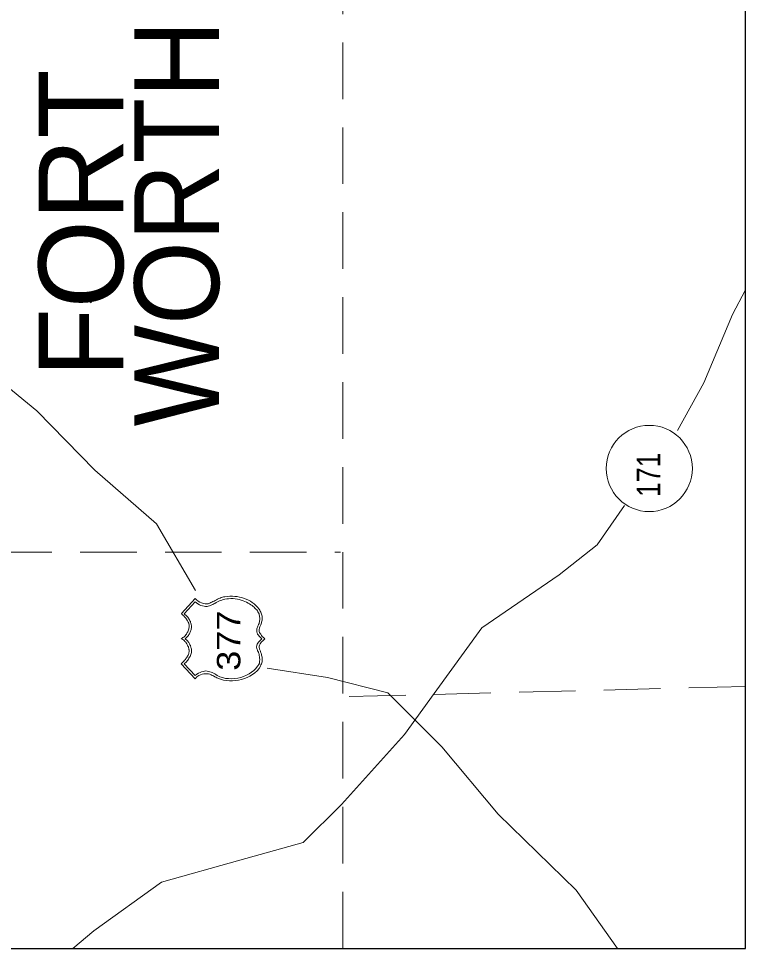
# Model space of a CAD drawing. Extents: x 2363323 to 2367082, y 6956018 to 6980837.
# Drawn here: x 2366076.4 to 2366234.3, y 6956633 to 6956834.9 of the extents above; entities that cross this region are included whole.
import ezdxf

# ---------------------------------------------------------------- set-up
doc = ezdxf.new("R2010")
doc.units = 0
doc.header["$LTSCALE"] = 4.1
doc.linetypes.add('MEDIUM_DASHED', pattern=[4.5, 3, -1.5])
doc.layers.add('62', color=7, linetype='Continuous', lineweight=13)
doc.layers.add('63', color=7, linetype='Continuous', lineweight=13)

msp = doc.modelspace()

# ---------------------------------------------------------------- linework, layer by layer
at = {"layer": '62', "linetype": 'MEDIUM_DASHED'}
for p, q in [((2366146.841, 6956632.956), (2366146.84, 6957082.55)), ((2365960.571, 6956719.006), (2366146.277, 6956719.029)), ((2366234.284, 6956689.842), (2366146.571, 6956687.637))]:
    msp.add_line(p, q, dxfattribs=at)
at = {"layer": '62'}
for p, q in [((2366093.962, 6956775.372), (2366091.959, 6956773.214)), ((2366225.284, 6956755.839), (2366219.503, 6956745.447)), ((2366202.061, 6956720.602), (2366208.046, 6956729.152)), ((2366106.337, 6956725.194), (2366114.819, 6956710.725)), ((2366193.803, 6956714.122), (2366202.061, 6956720.602))]:
    msp.add_line(p, q, dxfattribs=at)
at = {"layer": '62', "lineweight": 25}
msp.add_lwpolyline([(2365769.011, 6956632.956), (2366234.284, 6956632.956), (2366234.284, 6957082.548), (2365769.009, 6957082.548)], dxfattribs=at)
at = {"layer": '62'}
for points in [[(2366225.284, 6956755.839), (2366231.494, 6956770.67), (2366234.285, 6956775.98)], [(2366064.711, 6956763.894), (2366072.967, 6956755.728), (2366080.301, 6956749.743), (2366092.906, 6956736.826), (2366106.337, 6956725.194)], [(2366088.135, 6956632.958), (2366092.726, 6956636.76), (2366107.419, 6956647.359), (2366124.43, 6956652.129), (2366138.155, 6956655.932), (2366146.547, 6956664.212), (2366160.232, 6956679.424), (2366166.645, 6956688.357), (2366177.039, 6956702.6), (2366193.803, 6956714.122)], [(2366114.707, 6956691.53), (2366111.715, 6956694.792), (2366111.896, 6956694.972), (2366112.121, 6956695.174), (2366112.277, 6956695.354), (2366112.436, 6956695.534), (2366112.593, 6956695.714), (2366112.729, 6956695.917), (2366112.862, 6956696.097), (2366112.999, 6956696.277), (2366113.089, 6956696.457), (2366113.177, 6956696.637), (2366113.267, 6956696.838), (2366113.312, 6956697.02), (2366113.357, 6956697.222), (2366113.401, 6956697.38), (2366113.403, 6956697.582), (2366113.402, 6956697.784), (2366113.357, 6956697.92), (2366113.312, 6956698.077), (2366113.289, 6956698.257), (2366113.245, 6956698.437), (2366113.155, 6956698.618), (2366113.087, 6956698.797), (2366112.999, 6956698.954), (2366112.909, 6956699.134), (2366112.772, 6956699.316), (2366112.659, 6956699.474), (2366112.502, 6956699.63), (2366112.389, 6956699.787), (2366112.233, 6956699.924), (2366112.075, 6956700.034), (2366111.896, 6956700.124), (2366111.715, 6956700.216), (2366111.896, 6956700.327), (2366112.075, 6956700.462), (2366112.255, 6956700.574), (2366112.391, 6956700.734), (2366112.549, 6956700.868), (2366112.682, 6956701.047), (2366112.819, 6956701.227), (2366112.931, 6956701.384), (2366113.019, 6956701.566), (2366113.133, 6956701.748), (2366113.199, 6956701.95), (2366113.269, 6956702.128), (2366113.312, 6956702.355), (2366113.359, 6956702.511), (2366113.402, 6956702.736), (2366113.426, 6956702.938), (2366113.425, 6956703.096), (2366113.402, 6956703.274), (2366113.359, 6956703.432), (2366113.313, 6956703.638), (2366113.223, 6956703.794), (2366113.133, 6956703.974), (2366113.042, 6956704.132), (2366112.929, 6956704.311), (2366112.817, 6956704.467), (2366112.682, 6956704.672), (2366112.547, 6956704.83), (2366112.391, 6956705.007), (2366112.232, 6956705.168), (2366112.052, 6956705.368), (2366111.896, 6956705.504), (2366111.716, 6956705.684), (2366114.707, 6956708.948), (2366115.023, 6956708.654), (2366115.359, 6956708.361), (2366115.742, 6956708.158), (2366116.126, 6956708.001), (2366116.509, 6956707.866), (2366116.869, 6956707.798), (2366117.139, 6956707.776), (2366117.363, 6956707.8), (2366117.521, 6956707.822), (2366117.725, 6956707.912), (2366117.902, 6956707.978), (2366118.13, 6956708.068), (2366118.357, 6956708.181), (2366118.58, 6956708.295), (2366118.827, 6956708.408), (2366119.075, 6956708.541), (2366119.347, 6956708.676), (2366119.593, 6956708.812), (2366119.887, 6956708.946), (2366120.133, 6956709.058), (2366120.38, 6956709.148), (2366120.65, 6956709.216), (2366120.899, 6956709.306), (2366121.147, 6956709.328), (2366121.73, 6956709.42), (2366122.271, 6956709.464), (2366122.81, 6956709.464), (2366123.35, 6956709.418), (2366123.869, 6956709.374), (2366124.385, 6956709.26), (2366124.856, 6956709.148), (2366125.353, 6956708.99), (2366125.827, 6956708.811), (2366126.299, 6956708.586)], [(2366127.087, 6956707.416), (2366126.837, 6956707.596), (2366126.545, 6956707.797), (2366126.207, 6956707.978), (2366125.894, 6956708.136), (2366125.51, 6956708.294), (2366125.129, 6956708.451), (2366124.747, 6956708.608), (2366124.317, 6956708.721), (2366123.891, 6956708.811), (2366123.44, 6956708.878), (2366122.967, 6956708.946), (2366122.495, 6956708.944), (2366122, 6956708.901), (2366121.573, 6956708.854), (2366121.191, 6956708.811), (2366120.831, 6956708.721), (2366120.494, 6956708.631), (2366120.157, 6956708.498), (2366119.863, 6956708.361), (2366119.57, 6956708.248), (2366119.3, 6956708.091), (2366119.03, 6956707.911), (2366118.807, 6956707.798), (2366118.559, 6956707.664), (2366118.311, 6956707.551), (2366118.063, 6956707.438), (2366117.813, 6956707.371), (2366117.566, 6956707.304), (2366117.296, 6956707.258), (2366116.981, 6956707.258), (2366116.642, 6956707.304), (2366116.305, 6956707.371), (2366115.967, 6956707.461), (2366115.631, 6956707.598), (2366115.316, 6956707.798), (2366115.022, 6956708.002), (2366114.731, 6956708.25), (2366112.323, 6956705.661), (2366112.503, 6956705.504), (2366112.661, 6956705.368), (2366112.817, 6956705.211), (2366112.975, 6956705.054), (2366113.111, 6956704.875), (2366113.246, 6956704.694), (2366113.357, 6956704.515), (2366113.469, 6956704.334), (2366113.559, 6956704.131), (2366113.672, 6956703.951), (2366113.741, 6956703.748), (2366113.786, 6956703.591), (2366113.852, 6956703.39), (2366113.876, 6956703.231), (2366113.897, 6956703.096), (2366113.919, 6956702.937), (2366113.899, 6956702.781), (2366113.899, 6956702.578), (2366113.875, 6956702.398), (2366113.852, 6956702.218), (2366113.786, 6956702.016), (2366113.717, 6956701.858), (2366113.649, 6956701.656), (2366113.559, 6956701.476), (2366113.469, 6956701.318), (2366113.379, 6956701.114), (2366113.267, 6956700.958), (2366113.132, 6956700.8), (2366113.019, 6956700.62), (2366112.862, 6956700.507), (2366112.706, 6956700.35), (2366112.526, 6956700.214), (2366112.705, 6956700.08), (2366112.862, 6956699.967), (2366112.976, 6956699.81), (2366113.111, 6956699.676), (2366113.199, 6956699.54), (2366113.312, 6956699.406), (2366113.425, 6956699.224), (2366113.515, 6956699.11), (2366113.582, 6956698.932), (2366113.672, 6956698.774), (2366113.719, 6956698.618), (2366113.785, 6956698.46), (2366113.807, 6956698.3), (2366113.875, 6956698.146), (2366113.899, 6956697.966), (2366113.921, 6956697.807), (2366113.942, 6956697.627), (2366113.942, 6956697.402), (2366113.897, 6956697.222), (2366113.852, 6956696.998), (2366113.785, 6956696.796), (2366113.695, 6956696.57), (2366113.605, 6956696.367), (2366113.492, 6956696.187), (2366113.379, 6956695.984), (2366113.245, 6956695.761), (2366113.132, 6956695.58), (2366112.976, 6956695.422), (2366112.817, 6956695.22), (2366112.661, 6956695.062)], [(2366126.299, 6956708.586), (2366126.727, 6956708.362), (2366127.131, 6956708.068), (2366127.535, 6956707.778), (2366127.895, 6956707.416), (2366128.255, 6956707.056), (2366128.593, 6956706.674), (2366128.751, 6956706.448), (2366128.863, 6956706.246), (2366128.975, 6956705.998), (2366129.067, 6956705.774), (2366129.155, 6956705.571), (2366129.177, 6956705.346), (2366129.245, 6956705.098), (2366129.269, 6956704.896), (2366129.29, 6956704.671), (2366129.269, 6956704.446), (2366129.245, 6956704.244), (2366129.223, 6956704.042), (2366129.155, 6956703.816), (2366129.133, 6956703.658), (2366129.067, 6956703.456), (2366128.975, 6956703.276), (2366128.907, 6956703.118), (2366128.864, 6956702.94), (2366128.774, 6956702.782), (2366128.707, 6956702.625), (2366128.683, 6956702.466), (2366128.639, 6956702.308), (2366128.593, 6956702.128), (2366128.615, 6956701.948), (2366128.66, 6956701.768), (2366128.727, 6956701.588), (2366128.84, 6956701.384), (2366128.954, 6956701.204), (2366129.134, 6956700.957), (2366129.313, 6956700.732), (2366129.583, 6956700.507), (2366129.875, 6956700.214), (2366129.607, 6956699.967), (2366129.381, 6956699.72), (2366129.157, 6956699.517), (2366129.021, 6956699.314), (2366128.863, 6956699.134), (2366128.773, 6956698.956), (2366128.705, 6956698.797), (2366128.66, 6956698.64), (2366128.637, 6956698.527), (2366128.637, 6956698.348), (2366128.639, 6956698.234), (2366128.705, 6956698.077), (2366128.729, 6956697.942), (2366128.75, 6956697.807), (2366128.84, 6956697.651), (2366128.885, 6956697.49), (2366128.953, 6956697.38), (2366128.997, 6956697.2), (2366129.067, 6956697.02), (2366129.133, 6956696.841), (2366129.157, 6956696.637), (2366129.177, 6956696.457), (2366129.245, 6956696.254), (2366129.267, 6956696.054), (2366129.269, 6956695.827), (2366129.267, 6956695.647), (2366129.267, 6956695.422), (2366129.247, 6956695.174), (2366129.177, 6956694.972), (2366129.133, 6956694.747), (2366129.021, 6956694.522), (2366128.909, 6956694.298), (2366128.593, 6956693.78), (2366128.163, 6956693.284), (2366127.693, 6956692.834), (2366127.175, 6956692.43), (2366126.613, 6956692.07), (2366126.051, 6956691.777), (2366125.42, 6956691.552), (2366124.769, 6956691.35), (2366124.115, 6956691.216), (2366123.464, 6956691.124), (2366122.81, 6956691.057), (2366122.157, 6956691.058), (2366121.483, 6956691.124), (2366120.875, 6956691.237), (2366120.223, 6956691.417), (2366119.66, 6956691.64), (2366119.437, 6956691.732), (2366119.189, 6956691.844), (2366118.964, 6956691.978), (2366118.717, 6956692.137), (2366118.445, 6956692.25), (2366118.175, 6956692.384), (2366117.881, 6956692.52), (2366117.59, 6956692.587), (2366117.272, 6956692.632), (2366116.936, 6956692.632), (2366116.597, 6956692.634), (2366116.259, 6956692.52), (2366115.898, 6956692.407), (2366115.496, 6956692.204)], [(2366112.367, 6956694.794), (2366114.729, 6956692.227), (2366115.089, 6956692.52), (2366115.473, 6956692.722), (2366115.789, 6956692.902), (2366116.102, 6956693.037), (2366116.439, 6956693.127), (2366116.755, 6956693.172), (2366117.026, 6956693.217), (2366117.319, 6956693.174), (2366117.611, 6956693.128), (2366117.881, 6956693.06), (2366118.177, 6956692.97), (2366118.445, 6956692.857), (2366118.693, 6956692.744), (2366118.963, 6956692.586), (2366119.21, 6956692.431), (2366119.48, 6956692.272), (2366120.067, 6956691.98), (2366120.695, 6956691.778), (2366121.304, 6956691.62), (2366121.977, 6956691.552), (2366122.651, 6956691.53), (2366123.307, 6956691.552), (2366123.98, 6956691.663), (2366124.61, 6956691.82), (2366125.239, 6956692.024), (2366125.87, 6956692.296), (2366126.433, 6956692.586), (2366126.974, 6956692.947), (2366127.445, 6956693.33), (2366127.895, 6956693.756), (2366128.255, 6956694.231), (2366128.593, 6956694.724), (2366128.615, 6956694.838), (2366128.683, 6956694.951), (2366128.705, 6956695.106), (2366128.707, 6956695.287), (2366128.729, 6956695.444), (2366128.75, 6956695.602), (2366128.75, 6956695.784), (2366128.727, 6956695.984), (2366128.705, 6956696.166), (2366128.705, 6956696.344), (2366128.66, 6956696.526), (2366128.637, 6956696.704), (2366128.593, 6956696.884), (2366128.547, 6956697.042), (2366128.48, 6956697.2), (2366128.459, 6956697.334), (2366128.367, 6956697.492), (2366128.3, 6956697.627), (2366128.233, 6956697.762), (2366128.167, 6956697.898), (2366128.121, 6956698.077), (2366128.097, 6956698.19), (2366128.053, 6956698.347), (2366128.053, 6956698.528), (2366128.097, 6956698.684), (2366128.143, 6956698.887), (2366128.211, 6956699.067), (2366128.323, 6956699.226), (2366128.457, 6956699.451), (2366128.683, 6956699.676), (2366128.907, 6956699.944), (2366129.177, 6956700.192), (2366128.885, 6956700.507), (2366128.637, 6956700.778), (2366128.457, 6956701.002), (2366128.3, 6956701.25), (2366128.21, 6956701.474), (2366128.143, 6956701.654), (2366128.099, 6956701.858), (2366128.097, 6956702.06), (2366128.097, 6956702.241), (2366128.143, 6956702.398), (2366128.211, 6956702.578), (2366128.255, 6956702.758), (2366128.345, 6956702.938), (2366128.437, 6956703.118), (2366128.48, 6956703.298), (2366128.593, 6956703.5), (2366128.637, 6956703.704), (2366128.707, 6956703.93), (2366128.729, 6956704.131), (2366128.751, 6956704.332), (2366128.75, 6956704.558), (2366128.751, 6956704.784), (2366128.729, 6956704.988), (2366128.705, 6956705.211), (2366128.639, 6956705.436), (2366128.593, 6956705.64), (2366128.457, 6956705.842), (2366128.367, 6956706.066), (2366128.233, 6956706.248), (2366128.099, 6956706.471), (2366127.917, 6956706.674), (2366127.717, 6956706.876), (2366127.557, 6956707.058), (2366127.31, 6956707.215), (2366127.087, 6956707.416)], [(2366112.661, 6956695.062), (2366112.502, 6956694.927), (2366112.367, 6956694.794)], [(2366130.394, 6956693.802), (2366143.465, 6956691.824), (2366156.585, 6956688.492), (2366168.287, 6956676.768), (2366180.593, 6956662.119), (2366197.493, 6956645.582), (2366206.517, 6956632.956)], [(2366115.496, 6956692.204), (2366115.112, 6956691.914), (2366114.707, 6956691.53)]]:
    msp.add_lwpolyline(points, dxfattribs=at)
msp.add_circle((2366213.389, 6956737.212), 9.364, dxfattribs=at)
at = {"layer": '63', "linetype": 'MEDIUM_DASHED'}
for p, q in [((2366146.841, 6956632.956), (2366146.84, 6957082.55)), ((2365960.571, 6956719.006), (2366146.277, 6956719.029)), ((2366234.284, 6956689.842), (2366146.571, 6956687.637))]:
    msp.add_line(p, q, dxfattribs=at)
at = {"layer": '63'}
for p, q in [((2366093.962, 6956775.372), (2366091.959, 6956773.214)), ((2366225.284, 6956755.839), (2366219.503, 6956745.447)), ((2366202.061, 6956720.602), (2366208.046, 6956729.152)), ((2366106.337, 6956725.194), (2366114.819, 6956710.725)), ((2366193.803, 6956714.122), (2366202.061, 6956720.602))]:
    msp.add_line(p, q, dxfattribs=at)
at = {"layer": '63', "lineweight": 25}
msp.add_lwpolyline([(2365769.011, 6956632.956), (2366234.284, 6956632.956), (2366234.284, 6957082.548), (2365769.009, 6957082.548)], dxfattribs=at)
at = {"layer": '63'}
for points in [[(2366225.284, 6956755.839), (2366231.494, 6956770.67), (2366234.285, 6956775.98)], [(2366064.711, 6956763.894), (2366072.967, 6956755.728), (2366080.301, 6956749.743), (2366092.906, 6956736.826), (2366106.337, 6956725.194)], [(2366088.135, 6956632.958), (2366092.726, 6956636.76), (2366107.419, 6956647.359), (2366124.43, 6956652.129), (2366138.155, 6956655.932), (2366146.547, 6956664.212), (2366160.232, 6956679.424), (2366166.645, 6956688.357), (2366177.039, 6956702.6), (2366193.803, 6956714.122)], [(2366114.707, 6956691.53), (2366111.715, 6956694.792), (2366111.896, 6956694.972), (2366112.121, 6956695.174), (2366112.277, 6956695.354), (2366112.436, 6956695.534), (2366112.593, 6956695.714), (2366112.729, 6956695.917), (2366112.862, 6956696.097), (2366112.999, 6956696.277), (2366113.089, 6956696.457), (2366113.177, 6956696.637), (2366113.267, 6956696.838), (2366113.312, 6956697.02), (2366113.357, 6956697.222), (2366113.401, 6956697.38), (2366113.403, 6956697.582), (2366113.402, 6956697.784), (2366113.357, 6956697.92), (2366113.312, 6956698.077), (2366113.289, 6956698.257), (2366113.245, 6956698.437), (2366113.155, 6956698.618), (2366113.087, 6956698.797), (2366112.999, 6956698.954), (2366112.909, 6956699.134), (2366112.772, 6956699.316), (2366112.659, 6956699.474), (2366112.502, 6956699.63), (2366112.389, 6956699.787), (2366112.233, 6956699.924), (2366112.075, 6956700.034), (2366111.896, 6956700.124), (2366111.715, 6956700.216), (2366111.896, 6956700.327), (2366112.075, 6956700.462), (2366112.255, 6956700.574), (2366112.391, 6956700.734), (2366112.549, 6956700.868), (2366112.682, 6956701.047), (2366112.819, 6956701.227), (2366112.931, 6956701.384), (2366113.019, 6956701.566), (2366113.133, 6956701.748), (2366113.199, 6956701.95), (2366113.269, 6956702.128), (2366113.312, 6956702.355), (2366113.359, 6956702.511), (2366113.402, 6956702.736), (2366113.426, 6956702.938), (2366113.425, 6956703.096), (2366113.402, 6956703.274), (2366113.359, 6956703.432), (2366113.313, 6956703.638), (2366113.223, 6956703.794), (2366113.133, 6956703.974), (2366113.042, 6956704.132), (2366112.929, 6956704.311), (2366112.817, 6956704.467), (2366112.682, 6956704.672), (2366112.547, 6956704.83), (2366112.391, 6956705.007), (2366112.232, 6956705.168), (2366112.052, 6956705.368), (2366111.896, 6956705.504), (2366111.716, 6956705.684), (2366114.707, 6956708.948), (2366115.023, 6956708.654), (2366115.359, 6956708.361), (2366115.742, 6956708.158), (2366116.126, 6956708.001), (2366116.509, 6956707.866), (2366116.869, 6956707.798), (2366117.139, 6956707.776), (2366117.363, 6956707.8), (2366117.521, 6956707.822), (2366117.725, 6956707.912), (2366117.902, 6956707.978), (2366118.13, 6956708.068), (2366118.357, 6956708.181), (2366118.58, 6956708.295), (2366118.827, 6956708.408), (2366119.075, 6956708.541), (2366119.347, 6956708.676), (2366119.593, 6956708.812), (2366119.887, 6956708.946), (2366120.133, 6956709.058), (2366120.38, 6956709.148), (2366120.65, 6956709.216), (2366120.899, 6956709.306), (2366121.147, 6956709.328), (2366121.73, 6956709.42), (2366122.271, 6956709.464), (2366122.81, 6956709.464), (2366123.35, 6956709.418), (2366123.869, 6956709.374), (2366124.385, 6956709.26), (2366124.856, 6956709.148), (2366125.353, 6956708.99), (2366125.827, 6956708.811), (2366126.299, 6956708.586)], [(2366127.087, 6956707.416), (2366126.837, 6956707.596), (2366126.545, 6956707.797), (2366126.207, 6956707.978), (2366125.894, 6956708.136), (2366125.51, 6956708.294), (2366125.129, 6956708.451), (2366124.747, 6956708.608), (2366124.317, 6956708.721), (2366123.891, 6956708.811), (2366123.44, 6956708.878), (2366122.967, 6956708.946), (2366122.495, 6956708.944), (2366122, 6956708.901), (2366121.573, 6956708.854), (2366121.191, 6956708.811), (2366120.831, 6956708.721), (2366120.494, 6956708.631), (2366120.157, 6956708.498), (2366119.863, 6956708.361), (2366119.57, 6956708.248), (2366119.3, 6956708.091), (2366119.03, 6956707.911), (2366118.807, 6956707.798), (2366118.559, 6956707.664), (2366118.311, 6956707.551), (2366118.063, 6956707.438), (2366117.813, 6956707.371), (2366117.566, 6956707.304), (2366117.296, 6956707.258), (2366116.981, 6956707.258), (2366116.642, 6956707.304), (2366116.305, 6956707.371), (2366115.967, 6956707.461), (2366115.631, 6956707.598), (2366115.316, 6956707.798), (2366115.022, 6956708.002), (2366114.731, 6956708.25), (2366112.323, 6956705.661), (2366112.503, 6956705.504), (2366112.661, 6956705.368), (2366112.817, 6956705.211), (2366112.975, 6956705.054), (2366113.111, 6956704.875), (2366113.246, 6956704.694), (2366113.357, 6956704.515), (2366113.469, 6956704.334), (2366113.559, 6956704.131), (2366113.672, 6956703.951), (2366113.741, 6956703.748), (2366113.786, 6956703.591), (2366113.852, 6956703.39), (2366113.876, 6956703.231), (2366113.897, 6956703.096), (2366113.919, 6956702.937), (2366113.899, 6956702.781), (2366113.899, 6956702.578), (2366113.875, 6956702.398), (2366113.852, 6956702.218), (2366113.786, 6956702.016), (2366113.717, 6956701.858), (2366113.649, 6956701.656), (2366113.559, 6956701.476), (2366113.469, 6956701.318), (2366113.379, 6956701.114), (2366113.267, 6956700.958), (2366113.132, 6956700.8), (2366113.019, 6956700.62), (2366112.862, 6956700.507), (2366112.706, 6956700.35), (2366112.526, 6956700.214), (2366112.705, 6956700.08), (2366112.862, 6956699.967), (2366112.976, 6956699.81), (2366113.111, 6956699.676), (2366113.199, 6956699.54), (2366113.312, 6956699.406), (2366113.425, 6956699.224), (2366113.515, 6956699.11), (2366113.582, 6956698.932), (2366113.672, 6956698.774), (2366113.719, 6956698.618), (2366113.785, 6956698.46), (2366113.807, 6956698.3), (2366113.875, 6956698.146), (2366113.899, 6956697.966), (2366113.921, 6956697.807), (2366113.942, 6956697.627), (2366113.942, 6956697.402), (2366113.897, 6956697.222), (2366113.852, 6956696.998), (2366113.785, 6956696.796), (2366113.695, 6956696.57), (2366113.605, 6956696.367), (2366113.492, 6956696.187), (2366113.379, 6956695.984), (2366113.245, 6956695.761), (2366113.132, 6956695.58), (2366112.976, 6956695.422), (2366112.817, 6956695.22), (2366112.661, 6956695.062)], [(2366126.299, 6956708.586), (2366126.727, 6956708.362), (2366127.131, 6956708.068), (2366127.535, 6956707.778), (2366127.895, 6956707.416), (2366128.255, 6956707.056), (2366128.593, 6956706.674), (2366128.751, 6956706.448), (2366128.863, 6956706.246), (2366128.975, 6956705.998), (2366129.067, 6956705.774), (2366129.155, 6956705.571), (2366129.177, 6956705.346), (2366129.245, 6956705.098), (2366129.269, 6956704.896), (2366129.29, 6956704.671), (2366129.269, 6956704.446), (2366129.245, 6956704.244), (2366129.223, 6956704.042), (2366129.155, 6956703.816), (2366129.133, 6956703.658), (2366129.067, 6956703.456), (2366128.975, 6956703.276), (2366128.907, 6956703.118), (2366128.864, 6956702.94), (2366128.774, 6956702.782), (2366128.707, 6956702.625), (2366128.683, 6956702.466), (2366128.639, 6956702.308), (2366128.593, 6956702.128), (2366128.615, 6956701.948), (2366128.66, 6956701.768), (2366128.727, 6956701.588), (2366128.84, 6956701.384), (2366128.954, 6956701.204), (2366129.134, 6956700.957), (2366129.313, 6956700.732), (2366129.583, 6956700.507), (2366129.875, 6956700.214), (2366129.607, 6956699.967), (2366129.381, 6956699.72), (2366129.157, 6956699.517), (2366129.021, 6956699.314), (2366128.863, 6956699.134), (2366128.773, 6956698.956), (2366128.705, 6956698.797), (2366128.66, 6956698.64), (2366128.637, 6956698.527), (2366128.637, 6956698.348), (2366128.639, 6956698.234), (2366128.705, 6956698.077), (2366128.729, 6956697.942), (2366128.75, 6956697.807), (2366128.84, 6956697.651), (2366128.885, 6956697.49), (2366128.953, 6956697.38), (2366128.997, 6956697.2), (2366129.067, 6956697.02), (2366129.133, 6956696.841), (2366129.157, 6956696.637), (2366129.177, 6956696.457), (2366129.245, 6956696.254), (2366129.267, 6956696.054), (2366129.269, 6956695.827), (2366129.267, 6956695.647), (2366129.267, 6956695.422), (2366129.247, 6956695.174), (2366129.177, 6956694.972), (2366129.133, 6956694.747), (2366129.021, 6956694.522), (2366128.909, 6956694.298), (2366128.593, 6956693.78), (2366128.163, 6956693.284), (2366127.693, 6956692.834), (2366127.175, 6956692.43), (2366126.613, 6956692.07), (2366126.051, 6956691.777), (2366125.42, 6956691.552), (2366124.769, 6956691.35), (2366124.115, 6956691.216), (2366123.464, 6956691.124), (2366122.81, 6956691.057), (2366122.157, 6956691.058), (2366121.483, 6956691.124), (2366120.875, 6956691.237), (2366120.223, 6956691.417), (2366119.66, 6956691.64), (2366119.437, 6956691.732), (2366119.189, 6956691.844), (2366118.964, 6956691.978), (2366118.717, 6956692.137), (2366118.445, 6956692.25), (2366118.175, 6956692.384), (2366117.881, 6956692.52), (2366117.59, 6956692.587), (2366117.272, 6956692.632), (2366116.936, 6956692.632), (2366116.597, 6956692.634), (2366116.259, 6956692.52), (2366115.898, 6956692.407), (2366115.496, 6956692.204)], [(2366112.367, 6956694.794), (2366114.729, 6956692.227), (2366115.089, 6956692.52), (2366115.473, 6956692.722), (2366115.789, 6956692.902), (2366116.102, 6956693.037), (2366116.439, 6956693.127), (2366116.755, 6956693.172), (2366117.026, 6956693.217), (2366117.319, 6956693.174), (2366117.611, 6956693.128), (2366117.881, 6956693.06), (2366118.177, 6956692.97), (2366118.445, 6956692.857), (2366118.693, 6956692.744), (2366118.963, 6956692.586), (2366119.21, 6956692.431), (2366119.48, 6956692.272), (2366120.067, 6956691.98), (2366120.695, 6956691.778), (2366121.304, 6956691.62), (2366121.977, 6956691.552), (2366122.651, 6956691.53), (2366123.307, 6956691.552), (2366123.98, 6956691.663), (2366124.61, 6956691.82), (2366125.239, 6956692.024), (2366125.87, 6956692.296), (2366126.433, 6956692.586), (2366126.974, 6956692.947), (2366127.445, 6956693.33), (2366127.895, 6956693.756), (2366128.255, 6956694.231), (2366128.593, 6956694.724), (2366128.615, 6956694.838), (2366128.683, 6956694.951), (2366128.705, 6956695.106), (2366128.707, 6956695.287), (2366128.729, 6956695.444), (2366128.75, 6956695.602), (2366128.75, 6956695.784), (2366128.727, 6956695.984), (2366128.705, 6956696.166), (2366128.705, 6956696.344), (2366128.66, 6956696.526), (2366128.637, 6956696.704), (2366128.593, 6956696.884), (2366128.547, 6956697.042), (2366128.48, 6956697.2), (2366128.459, 6956697.334), (2366128.367, 6956697.492), (2366128.3, 6956697.627), (2366128.233, 6956697.762), (2366128.167, 6956697.898), (2366128.121, 6956698.077), (2366128.097, 6956698.19), (2366128.053, 6956698.347), (2366128.053, 6956698.528), (2366128.097, 6956698.684), (2366128.143, 6956698.887), (2366128.211, 6956699.067), (2366128.323, 6956699.226), (2366128.457, 6956699.451), (2366128.683, 6956699.676), (2366128.907, 6956699.944), (2366129.177, 6956700.192), (2366128.885, 6956700.507), (2366128.637, 6956700.778), (2366128.457, 6956701.002), (2366128.3, 6956701.25), (2366128.21, 6956701.474), (2366128.143, 6956701.654), (2366128.099, 6956701.858), (2366128.097, 6956702.06), (2366128.097, 6956702.241), (2366128.143, 6956702.398), (2366128.211, 6956702.578), (2366128.255, 6956702.758), (2366128.345, 6956702.938), (2366128.437, 6956703.118), (2366128.48, 6956703.298), (2366128.593, 6956703.5), (2366128.637, 6956703.704), (2366128.707, 6956703.93), (2366128.729, 6956704.131), (2366128.751, 6956704.332), (2366128.75, 6956704.558), (2366128.751, 6956704.784), (2366128.729, 6956704.988), (2366128.705, 6956705.211), (2366128.639, 6956705.436), (2366128.593, 6956705.64), (2366128.457, 6956705.842), (2366128.367, 6956706.066), (2366128.233, 6956706.248), (2366128.099, 6956706.471), (2366127.917, 6956706.674), (2366127.717, 6956706.876), (2366127.557, 6956707.058), (2366127.31, 6956707.215), (2366127.087, 6956707.416)], [(2366112.661, 6956695.062), (2366112.502, 6956694.927), (2366112.367, 6956694.794)], [(2366130.394, 6956693.802), (2366143.465, 6956691.824), (2366156.585, 6956688.492), (2366168.287, 6956676.768), (2366180.593, 6956662.119), (2366197.493, 6956645.582), (2366206.517, 6956632.956)], [(2366115.496, 6956692.204), (2366115.112, 6956691.914), (2366114.707, 6956691.53)]]:
    msp.add_lwpolyline(points, dxfattribs=at)
msp.add_circle((2366213.389, 6956737.212), 9.364, dxfattribs=at)

# ---------------------------------------------------------------- texts
at = {"layer": '62'}
for s, height, width, p in [('WORTH', 18.39, 0.95, (2366119.906, 6956746.345)), ('171', 5.099, 0.85, (2366215.785, 6956730.999)), ('377', 5.099, 1.15, (2366124.543, 6956693.263))]:
    msp.add_text(s, height=height, rotation=90, dxfattribs=dict(at, width=width)).set_placement(p)
msp.add_text('FORT', height=18.39, rotation=90, dxfattribs=at).set_placement((2366099.092, 6956756.989))
at = {"layer": '63'}
for s, height, width, p in [('WORTH', 18.39, 0.95, (2366119.906, 6956746.345)), ('171', 5.099, 0.85, (2366215.785, 6956730.999)), ('377', 5.099, 1.15, (2366124.543, 6956693.263))]:
    msp.add_text(s, height=height, rotation=90, dxfattribs=dict(at, width=width)).set_placement(p)
msp.add_text('FORT', height=18.39, rotation=90, dxfattribs=at).set_placement((2366099.092, 6956756.989))

doc.saveas('drawing.dxf')
